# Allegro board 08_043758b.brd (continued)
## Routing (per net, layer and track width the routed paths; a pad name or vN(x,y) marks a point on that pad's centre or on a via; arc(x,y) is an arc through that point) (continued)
IO_L15_34_TX_D1: length 23.2
  TOP w0.102: U4.R13 48.72,29.34 48.43,29.34 48.23,29.14 45.92,29.14 v2(45.53,28.75) ; U5.D11 v2(32.35,28.08)
  L6_SIG w0.114: v2(32.35,28.08) 32.67,28.08 32.74,28 32.74,27.88 32.95,27.68 34.94,27.68 35.41,28.14 37.69,28.14 38.45,27.38 39.2,27.38 39.35,27.52 39.35,28.12 39.49,28.27 39.7,28.27 39.84,28.12 39.84,27.52 39.99,27.38 40.19,27.38 40.34,27.52 40.34,28.12 40.48,28.27 40.69,28.27 40.83,28.12 40.83,27.52 40.98,27.38 41.18,27.38 41.33,27.52 41.33,28.12 41.47,28.27 41.68,28.27 41.83,28.12 41.83,27.52 41.97,27.38 44.04,27.38 44.43,27.76 44.43,28.35 44.83,28.75 v2(45.53,28.75)
IO_L16_34_TX_D2: length 22.7
  TOP w0.102: v2(46.43,27.75) U4.R15 ; U5.E11 31.53,28.09 31.53,28.08 v2(31.54,28.07)
  L6_SIG w0.114: v2(31.54,28.07) 31.54,27.78 31.64,27.68 31.74,27.68 31.94,27.48 31.94,26.98 32.56,26.36 35.66,26.36 35.89,26.59 35.89,27.13 36.04,27.28 36.24,27.28 36.39,27.13 36.39,26.82 36.59,26.62 44.42,26.62 45.41,27.61 45.77,27.61 46.18,27.19 47.07,27.19 47.27,27.39 47.27,27.57 47.09,27.75 v2(46.43,27.75)
IO_L16_34_TX_D3: length 23.6
  TOP w0.102: U4.P11 49.12,30.54 48.53,30.54 47.73,29.75 43.82,29.75 v2(42.82,28.75) ; U5.D10 v2(32.34,28.88)
  L6_SIG w0.114: v2(32.34,28.88) 32.74,29.28 35.65,29.28 35.95,28.98 36.95,28.98 37.55,29.58 37.79,29.58 37.94,29.43 37.94,29.07 38.08,28.92 38.29,28.92 38.43,29.07 38.43,29.43 38.58,29.58 38.78,29.58 38.93,29.43 38.93,29.19 39.07,29.05 39.28,29.05 39.42,29.19 39.42,29.43 39.57,29.58 39.77,29.58 39.92,29.43 39.92,29.19 40.06,29.05 40.27,29.05 40.41,29.19 40.41,29.43 40.56,29.58 40.76,29.58 40.91,29.43 40.91,29.19 41.05,29.05 41.26,29.05 41.49,29.28 43.28,29.28 43.41,29.16 43.41,28.9 43.25,28.75 v2(42.82,28.75)
IO_L17_34_TX_D4: length 23.2
  TOP w0.102: U4.R11 48.33,30.95 v2(47.53,30.15) ; U5.E10 v2(31.54,28.88)
  L6_SIG w0.114: v2(31.54,28.88) 31.54,28.55 31.62,28.48 31.74,28.48 31.94,28.28 31.94,27.88 32.15,27.68 32.55,27.68 32.74,27.48 32.74,26.98 32.95,26.78 35.15,26.78 35.41,27.04 35.41,27.34 35.7,27.63 37.59,27.63 38.23,27 44.3,27 44.85,27.56 44.85,28.06 45.07,28.28 46.96,28.28 47.96,29.28 47.96,29.72 v2(47.53,30.15)
IO_L17_34_TX_D5: length 22.7
  TOP w0.102: U5.D9 v2(32.34,29.68) ; U4.R12 48.15,29.57 48.13,29.57 48,29.45 44.52,29.45 v2(43.83,28.75)
  L6_SIG w0.114: v2(32.34,29.68) 32.75,30.08 35.35,30.08 36.05,29.38 36.75,29.38 37.35,29.98 41.06,29.98 41.37,29.66 43.6,29.66 43.93,29.99 43.93,30.3 44.08,30.45 44.93,30.45 45.31,30.06 45.31,29.74 44.32,28.75 v2(43.83,28.75)
IO_L18_34_TX_D6: length 22.9
  TOP w0.102: U4.P14 49.13,28.14 49.13,27.55 48.95,27.37 44.4,27.37 v2(43.83,27.95) ; U5.E9 v2(31.54,29.68)
  L6_SIG w0.114: v2(43.83,27.95) 43.21,27.95 43.03,27.76 42.52,27.76 42.26,28.01 42.26,28.67 42.05,28.88 41.73,28.88 41.5,28.65 39.09,28.65 38.87,28.43 38.87,28 38.75,27.88 38.48,27.88 38.35,28 38.35,28.38 38.21,28.52 35.2,28.52 34.85,28.88 34.6,28.88 34.46,28.73 34.46,28.62 34.31,28.48 32.19,28.48 31.94,28.72 31.94,29.28 v2(31.54,29.68)
IO_L18_34_TX_D7: length 22.7
  TOP w0.102: U4.P13 49.12,28.94 48.42,28.94 48.23,28.75 46.63,28.75 46.63,28.75 v2(46.42,28.75) ; U5.D8 v2(32.34,30.48)
  L6_SIG w0.114: v2(46.42,28.75) 46.92,28.75 47.13,28.95 47.13,30.25 46.93,30.45 46.6,30.45 46.33,30.17 45.76,30.17 45.05,30.88 42.72,30.88 42.58,30.74 42.58,30.52 42.43,30.38 42.23,30.38 42.08,30.52 42.08,30.74 41.94,30.88 41.6,30.88 41.46,30.74 41.46,30.52 41.31,30.38 35.65,30.38 35.15,30.88 32.75,30.88 v2(32.34,30.48)
IO_L19_34_TX_D8: length 22.6
  TOP w0.102: v2(47.42,31.75) 47.82,32.15 49.93,32.15 U4.N9 ; U5.E8 v2(31.54,30.48)
  L6_SIG w0.114: v2(47.42,31.75) 44.93,31.75 44.86,31.68 38.85,31.68 38.71,31.82 37.69,31.82 37.45,31.58 37.45,31.32 37.31,31.18 37.1,31.18 36.96,31.32 36.96,31.63 36.81,31.78 36.6,31.78 36.46,31.63 36.46,31.32 36.31,31.18 36.11,31.18 35.96,31.32 35.96,31.76 35.75,31.98 32.45,31.98 31.94,31.47 31.94,30.88 v2(31.54,30.48)
IO_L19_34_TX_D9: length 23.4
  TOP w0.102: v2(49.93,32.95) 50.73,32.95 U4.M9 ; U5.D7 v2(32.34,31.28)
  L6_SIG w0.114: v2(49.93,32.95) 49.93,32.55 49.53,32.15 48.03,32.15 47.83,31.95 47.83,31.55 47.63,31.36 45.43,31.36 45.36,31.28 41.35,31.28 40.85,30.78 40.54,30.78 40.39,30.92 40.39,31.13 40.25,31.28 40.04,31.28 39.9,31.13 39.9,30.92 39.75,30.78 39.55,30.78 39.4,30.92 39.4,31.13 39.26,31.28 39.05,31.28 38.91,31.13 38.91,30.92 38.76,30.78 38.56,30.78 38.41,30.92 38.41,31.13 38.27,31.28 38.06,31.28 37.92,31.13 37.92,30.92 37.77,30.78 35.85,30.78 34.95,31.68 32.75,31.68 32.35,31.28 v2(32.34,31.28)
IO_L20_34_TX_D10: length 22.4
  TOP w0.102: v2(48.22,33.34) 48.23,33.35 U4.R8 ; U5.F8 v2(30.74,30.48)
  L6_SIG w0.114: v2(48.22,33.34) 48.13,33.05 47.83,32.75 47.83,32.35 47.62,32.15 45.37,32.15 45.06,32.46 45.06,33.02 44.85,33.22 36.04,33.22 35.56,33.71 34.17,33.71 33.94,33.48 33.94,33.03 33.39,32.48 32.14,32.48 31.68,32.02 31.48,32.02 31.14,31.68 31.14,30.88 30.75,30.48 v2(30.74,30.48)
IO_L20_34_TX_D11: length 22.8
  TOP w0.102: U4.R7 48.32,34.15 48.23,34.05 46.03,34.05 v2(44.53,32.55) ; U5.E7 v2(31.54,31.28)
  L6_SIG w0.114: v2(44.53,32.55) 44.53,32.21 44.4,32.08 40.49,32.08 40.33,32.24 40.33,32.66 40.19,32.81 39.98,32.81 39.84,32.66 39.84,32.26 39.69,32.11 39.49,32.11 39.34,32.26 39.34,32.54 39.2,32.68 38.99,32.68 38.85,32.54 38.85,32.38 38.7,32.24 38.5,32.24 38.35,32.38 38.35,32.54 38.21,32.68 38,32.68 37.86,32.54 37.86,32.38 37.71,32.24 37.51,32.24 37.36,32.38 37.36,32.54 37.22,32.68 37.01,32.68 36.87,32.54 36.87,32.38 36.72,32.24 36.14,32.24 35.52,32.85 34.4,32.85 33.79,32.24 32.31,32.24 31.85,31.78 31.65,31.78 31.54,31.68 v2(31.54,31.28)
IO_L21_34_CTRL_OUT4: length 32.1
  TOP w0.102: U4.M10 v2(50.73,31.35) ; U5.F6 v2(29.95,32.88)
  L5_SIG w0.114: v2(50.73,31.35) 51.13,30.95 51.13,30.34 50.93,30.14 48.93,30.14 48.26,29.47 46.91,29.47 45.93,30.45 45.53,30.45 44.02,31.95 44.02,32.85 43.26,33.61 43.26,34.38 41.27,36.38 36.57,36.38 35.28,37.67 32.1,37.67 31.6,37.16 31.6,36.73 31.14,36.28 31.14,33.47 30.95,33.28 30.35,33.28 v2(29.95,32.88)
IO_L21_34_CTRL_OUT5: length 30.6
  TOP w0.102: U5.F5 v2(29.95,33.67) ; U4.M11 v2(50.73,30.55)
  L5_SIG w0.114: v2(29.95,33.67) 30.34,34.07 30.34,34.68 29.95,35.08 29.95,36.65 31.72,38.43 40.55,38.43 45.23,33.75 45.23,32.31 45.69,31.85 46.33,31.85 47.03,31.15 47.03,30.88 47.36,30.54 47.93,30.54 48.34,30.95 50.33,30.95 v2(50.73,30.55)
IO_L22_34_CTRL_OUT6: length 32.3
  TOP w0.102: U5.F4 v2(29.94,34.48) ; v2(49.93,34.55) U4.N7
  L5_SIG w0.114: v2(29.94,34.48) 29.54,34.08 28.85,34.08 28.74,34.18 28.74,37.1 29.18,37.54 29.69,37.54 31.34,39.19 40.79,39.19 47.03,32.95 47.03,32.38 47.26,32.14 48.43,32.14 48.76,32.48 48.76,33.38 v2(49.93,34.55)
IO_L22_34_CTRL_OUT7: length 30.1
  TOP w0.102: U5.G4 v2(29.14,34.48) ; v2(49.93,33.75) U4.N8
  L5_SIG w0.114: v2(29.14,34.48) 29.55,34.88 29.55,36.76 31.6,38.81 40.67,38.81 46.23,33.25 46.23,32.35 47.23,31.34 48.73,31.34 49.53,32.15 49.53,33.35 v2(49.93,33.75)
IO_L23_35_SPI_CLK: length 70.5
  TOP w0.102: U5.J5 v2(27.55,33.68) ; U4.E11 v2(57.13,30.55)
  L5_SIG w0.114: v2(27.55,33.68) 27.15,33.28 24.56,33.28 21.91,30.62 21.91,23.61 28.17,17.35 34.52,17.35 35.28,16.58 42.14,16.58 42.77,17.22 54.18,17.22 54.47,17.51 57.92,17.51 58.83,18.42 58.83,25.95 59.33,26.45 59.33,28.05 59.13,28.25 59.13,30.74 58.93,30.95 57.53,30.95 v2(57.13,30.55)
IO_L23_35_SPI_ENB: length 66.4
  TOP w0.102: U4.E12 v2(57.13,29.75) ; U5.K6 v2(26.74,32.88)
  L5_SIG w0.114: v2(57.13,29.75) 57.53,30.15 58.13,30.15 58.33,29.95 58.33,28.44 59.03,27.74 59.03,26.65 58.53,26.15 58.53,18.76 57.67,17.89 54.09,17.89 53.8,17.6 42.52,17.6 41.88,16.96 37.56,16.96 36.93,17.6 28.42,17.6 22.21,23.81 22.21,30.5 24.18,32.48 26.34,32.48 v2(26.74,32.88)
IO_L24_35_SPI_DI: length 64.2
  TOP w0.102: U4.E13 v2(57.13,28.95) ; U5.J4 v2(27.54,34.48)
  L5_SIG w0.114: v2(27.54,34.48) U5.J4 27.94,32.38 27.24,31.68 24.23,31.68 23.55,30.99 23.55,30.78 23.77,30.56 23.77,30.35 23.63,30.21 23.42,30.21 23.2,30.43 22.99,30.43 22.8,30.24 22.8,24.24 28.67,18.36 53.29,18.36 53.58,18.65 57.26,18.65 57.93,19.32 57.93,27.94 57.23,28.64 v2(57.13,28.95)
IO_L24_35_SPI_DO: length 62.7
  TOP w0.102: U5.L6 v2(25.94,32.08) ; U4.F12 v2(56.33,29.75)
  L5_SIG w0.114: v2(25.94,32.08) 24.21,32.08 22.51,30.37 22.51,24.02 28.55,17.98 53.54,17.98 53.83,18.27 57.54,18.27 58.23,18.96 58.23,26.35 58.73,26.85 58.73,27.54 57.53,28.74 57.53,29.24 57.43,29.34 56.99,29.34 56.59,29.75 v2(56.33,29.75)
JTAG_TCK: length 49.9
  TOP w0.102: U4.G9 55.53,32.95 61.44,32.95 61.55,32.84 63.54,32.84 64.05,32.33 69.83,32.33 v1(70.34,31.82) ; TCK.1 60.3,8.71 62.84,8.71 P1.4
  L5_SIG w0.114: v1(70.34,31.82) 69.71,31.19 69.71,29.24 68.74,28.27 68.74,26.54 69.71,25.57 69.71,20.03 68.82,19.14 68.82,13.42 67.16,11.76 v1(67.16,11.12)
  BOTTOM w0.102: v1(67.16,11.12) 66.52,10.49 64.74,10.49 64.11,9.85 P1.4
JTAG_TDI: length 43.7
  TOP w0.102: TDI.1 69.82,6.8 69.82,7.44 69.06,8.2 67.41,8.2 P1.8 ; U4.L7 v2(51.53,34.55)
  L5_SIG w0.114: v2(51.53,34.55) 51.53,34.54 51.92,34.15 54.13,34.15 55.43,32.85 59.27,32.85 61.44,30.69 61.44,23.83 62.58,22.68 62.58,17.85 63.85,16.58 63.85,10.23 P1.8
JTAG_TDO: length 42.9
  TOP w0.102: TDO.1 69.82,8.07 69.19,8.71 66.65,8.71 P1.6 ; U4.L8 v2(51.53,33.75)
  L5_SIG w0.114: v2(51.53,33.75) 51.53,33.74 51.92,33.35 54.53,33.35 55.33,32.55 59.14,32.55 59.93,31.75 59.93,30.27 60.23,29.97 60.23,29.49 60.68,29.04 60.68,23.95 62.2,22.43 62.2,17.6 63.35,16.46 63.35,9.47 P1.6
JTAG_TMS: length 38.5
  TOP w0.102: P1.2 61.57,7.44 TMS.1 ; U4.L9 v2(51.53,32.95)
  L5_SIG w0.114: P1.2 62.84,16.33 61.82,17.35 61.82,22.17 60.3,23.7 60.3,28.84 59.92,29.22 59.92,29.93 59.53,30.31 59.53,31.35 59.13,31.75 52.73,31.75 v2(51.53,32.95)
PG_1P0V: length 21.6
  TOP w0.305: v1(92.94,21.92) 92.57,21.55 U3.16
  BOTTOM w0.203: v1(92.94,21.92) 93.7,22.68 93.7,30.48 89.76,34.41 89.76,37.67 89.13,38.3 R86.1
  BOTTOM w0.305: R6.2 v1(92.94,21.92)
PG_1P3V: length 94.8
  TOP w0.127: U12.4 v1(51.28,14.41) ; v2(58.73,32.15) 58.33,32.55 U4.C9 ; U7.5 v1(43.15,10.24) ; U1.5 22.28,10.91 22.45,10.74 v1(22.45,10.36)
  L5_SIG w0.127: v1(71.49,30.85) 71.49,30.46 70.47,29.45 70.47,28.91 71.24,28.14 71.24,26.41 70.47,25.64 v1(70.47,11.16)
  L6_SIG w0.127: v1(70.47,11.16) 69.58,10.27 63.74,10.27 58.91,15.1 55.87,15.1 55.18,14.41 v1(51.28,14.41) ; v1(71.49,30.85) 71.49,31.8 70.95,32.33 69.95,32.33 69.76,32.15 v2(58.73,32.15)
  BOTTOM w0.127: v1(22.45,10.36) 22.92,9.89 29.2,9.89 30,9.09 36.68,9.09 37.82,10.24 v1(43.15,10.24) 46.45,10.24 PG_1P3V.1 47.34,11.12 47.99,11.12 v1(51.28,14.41) ; v1(71.49,30.85) 71.49,31.44 R15.1 71.52,32.01 C47.1 72.95,32.01 R13.2
PG_1P8V: length 12
  TOP w0.203: v2(92.42,40.7) 92.3,41.05 U6.29 ; v2(91.79,47.49) 91.79,47.44 91.8,47.44 U6.13
  L5_SIG w0.305: v2(92.42,40.7) 92.42,41.08 94.21,42.87 94.21,46.3 93.57,46.94 92.3,46.94 91.79,47.44 v2(91.79,47.49)
  BOTTOM w0.305: R59.1 92.42,39.95 v2(92.42,40.7)
PG_1P35V: length 124.9
  TOP w0.127: v1(21.69,9.34) 21.05,9.98 U1.4 ; U7.4 42.22,9.64 42.52,9.34 v1(44.04,9.34)
  TOP w0.203: v2(92.43,48.21) 92.3,47.82 U6.12
  L5_SIG w0.127: v1(76.93,11.12) 76.19,11.87 76.19,16.75 77.71,18.27 77.71,19.54 79.36,21.19 79.36,27.29 79.87,27.8 79.87,32.88 85.58,38.59 85.58,45.32 88.47,48.21 v2(92.43,48.21)
  L6_SIG w0.127: v1(76.93,11.12) 76.55,11.5 71.98,11.5 70.24,9.76 63.49,9.76 59.04,14.21 57.14,14.21 56.63,13.7 50.66,13.7 47.99,11.03 44.97,11.03 44.04,10.11 v1(44.04,9.34)
  BOTTOM w0.127: v2(92.43,48.21) 92.43,47.44 91.92,46.94 85.44,46.94 83.54,45.03 R50.1 ; v1(21.69,9.34) 28.73,9.34 29.7,8.37 37.2,8.37 38.18,9.34 v1(44.04,9.34)
PL_GPIO0: length 50.1
  TOP w0.127: U4.K13 v2(52.33,28.95)
  L6_SIG w0.127: v2(52.33,28.95) 52.53,28.95 52.93,29.35 53.43,29.35 54.23,30.15 56.53,30.15 56.73,29.94 56.73,29.54 56.93,29.34 57.33,29.34 57.53,29.14 57.53,28.04 57.83,27.74 57.83,26.84 58.53,26.14 58.53,18.74 65.02,12.25 81.52,12.25 83.16,10.61 83.16,8.07 L10P.1
PL_GPIO1: length 55.5
  TOP w0.102: U4.M12 v2(50.73,29.75)
  L6_SIG w0.127: v2(50.73,29.75) 50.73,29.65 51.03,29.35 52.53,29.35 52.73,29.55 52.73,30.75 52.93,30.95 57.33,30.95 57.53,30.75 57.53,29.54 57.73,29.34 58.13,29.34 58.33,29.14 58.33,28.34 59.33,27.34 59.33,19.14 64.36,14.11 67.73,14.11 68.81,13.03 82.65,13.03 85.7,9.98 85.7,8.07 L12N.1
PL_GPIO2: length 52
  TOP w0.127: U4.R10 v2(48.25,31.75)
  L6_SIG w0.127: v2(48.25,31.75) 48.25,31.53 49.53,30.25 49.53,28.81 49.79,28.55 54.07,28.55 54.35,28.83 54.35,29.17 54.53,29.34 56.53,29.34 56.73,29.14 56.73,27.84 56.93,27.64 57.33,27.64 57.53,27.44 57.53,26.32 58.13,25.72 58.13,18.54 64.82,11.85 81.29,11.85 81.89,11.25 L24N.1
PS-SRST#: length 33.3
  TOP w0.127: v1(71.24,29.14) 70.04,29.14 69.84,28.94 64.23,28.94 63.74,29.44 R74.2 61.95,30.3 61.7,30.55 59.53,30.55 U4.B11 ; v2(75.54,44.38) U13.A4
  L5_SIG w0.127: v2(75.54,44.38) 75.54,32.24 73.44,30.14 72.24,30.14 v1(71.24,29.14)
PS_GPIO0: length 54.7
  TOP w0.102: U4.D8 v2(57.13,33.75)
  L5_SIG w0.127: v1(63.53,36.25) 62.73,35.45 60.03,35.45 59.23,34.65 58.63,34.65 58.13,34.15 57.53,34.15 v2(57.13,33.75)
  L6_SIG w0.127: v1(83.95,22.84) 84.35,22.44 84.35,18.57 92.05,10.87 MIO0.1
  BOTTOM w0.127: v1(83.95,22.84) 83.95,23.41 83.81,23.56 83.81,26.78 82.92,27.67 81.77,27.67 81.14,28.31 81.14,30.34 76.75,34.73 66.98,34.73 66.76,34.95 64.03,34.95 63.53,35.45 v1(63.53,36.25)
PS_GPIO1: length 55.8
  TOP w0.127: v1(72.34,29.14) 71.78,29.7 69.84,29.7 68.59,30.95 63.63,30.95 63.23,31.35 59.53,31.35 U4.B10
  L5_SIG w0.127: v1(72.34,29.14) 73.44,28.04 73.44,27.14 72.44,26.14 72.44,13.51 76.19,9.76 79.44,9.76 80.62,8.58 80.62,6.04 81.25,5.41 90.65,5.41 MIO10.1
PS_GPIO2: length 52.9
  TOP w0.127: U4.D6 v2(57.13,34.55)
  L5_SIG w0.127: v1(62.73,36.25) 62.23,35.75 59.73,35.75 58.93,34.95 57.53,34.95 v2(57.13,34.55)
  L6_SIG w0.127: v1(83.35,22.24) 83.35,18.93 89.51,12.77 MIO11.1
  BOTTOM w0.127: v1(62.73,36.25) 62.73,35.75 63.83,34.65 66.64,34.65 66.85,34.43 76.54,34.43 80.76,30.21 80.76,28.05 81.65,27.16 82.79,27.16 83.35,26.6 v1(83.35,22.24)
PS_GPIO3: length 51.1
  TOP w0.127: U4.B5 59.53,36.15 60.93,36.15 61.03,36.25 v1(61.73,36.25)
  L6_SIG w0.127: v1(82.15,22.24) 82.15,19.5 88.24,13.41 88.24,8.07 MIO09.1
  BOTTOM w0.127: v1(61.73,36.25) 63.63,34.35 66.54,34.35 66.74,34.15 76.31,34.15 80.38,30.08 80.38,27.8 82.15,26.03 v1(82.15,22.24)
PS_GPIO4: length 43.3
  TOP w0.127: U4.C13 v2(58.73,28.95)
  L6_SIG w0.127: v2(58.73,28.95) 58.73,28.45 60.93,26.24 60.93,18.14 63.43,15.63 66.75,15.63 68.97,13.41 85.19,13.41 86.97,11.63 MIO53.1
PS_GPIO5: length 45.8
  TOP w0.127: U4.D13 v2(57.93,28.95)
  L5_SIG w0.127: v1(83.16,11.5) 83.16,8.58 83.67,8.07 85.7,8.07 MIO49.1
  L6_SIG w0.127: v1(83.16,11.5) 82.01,12.65 68.68,12.65 67.62,13.71 64.16,13.71 58.93,18.94 58.93,27.24 57.93,28.24 v2(57.93,28.95)
PS_GPIO6: length 47
  TOP w0.127: v2(59.54,29.74) U4.B12
  L5_SIG w0.127: MIO48.1 86.08,11 v1(87.6,11)
  L6_SIG w0.127: v1(87.6,11) 87.6,12.39 86.21,13.79 69.19,13.79 66.95,16.03 63.63,16.03 61.33,18.34 61.33,26.34 59.13,28.54 59.13,29.34 v2(59.54,29.74)
PS_MIO01_500_QSPI0_SS_B: length 38.3
  TOP w0.127: U4.A5 64.13,35.75 64.54,36.15 65.14,36.15 65.89,36.9 65.89,39.5 68.35,41.97 v1(68.35,42.55) ; U13.C2 v2(72.61,48.31)
  L5_SIG w0.127: v2(72.61,48.31) 72.94,48.64 72.94,50.16 72.74,50.36 72.34,50.36 72.13,50.15 72.13,48.74 71.98,48.59 71.77,48.59 71.62,48.74 71.62,50.39 71.47,50.54 71.26,50.54 71.11,50.39 71.11,48.99 70.97,48.84 70.76,48.84 70.61,48.99 70.61,50.39 70.46,50.54 70.25,50.54 70.1,50.39 70.1,48.99 69.95,48.84 69.74,48.84 69.59,48.99 69.59,50.09 69.44,50.24 69.02,50.24 68.81,50.03 68.81,43 v1(68.35,42.55)
  BOTTOM w0.127: v2(72.61,48.31) 73.09,47.83 73.39,47.83 R14.2
PS_MIO02_500_QSPI0_IO0: length 33.8
  TOP w0.127: v1(74.14,33.6) 73.12,32.59 70.47,32.59 69.71,33.35 63.85,33.35 63.73,33.22 61.56,33.22 61.43,33.35 U4.A8 ; U13.D3 v2(70.61,47.31)
  L5_SIG w0.127: v1(74.14,33.6) 74.14,40.08 73.84,40.38 73.84,40.59 74.01,40.76 74.01,40.97 73.86,41.12 73.65,41.12 73.48,40.95 73.27,40.95 73.04,41.18 73.04,41.39 73.27,41.62 73.27,41.83 73.13,41.98 72.91,41.98 72.68,41.75 72.47,41.75 72.24,41.98 72.24,46.3 71.23,47.31 v2(70.61,47.31)
  BOTTOM w0.127: v2(70.61,47.31) 69.93,47.31 R120.1
PS_MIO03_500_QSPI0_IO1: length 37.5
  TOP w0.127: U4.A7 60.36,33.72 v2(61.65,33.72) ; U13.D2 v2(70.61,48.31)
  L5_SIG w0.127: v2(61.65,33.72) 61.65,34.32 61.95,34.62 63.09,34.62 64.05,35.57 64.26,35.57 64.87,34.96 65.08,34.96 65.23,35.1 65.23,35.32 64.61,35.93 64.61,36.14 64.76,36.29 64.97,36.29 65.89,35.37 66.1,35.37 66.25,35.52 66.25,35.73 65.33,36.65 65.33,36.86 65.48,37.01 65.69,37.01 66.31,36.39 66.52,36.39 66.67,36.54 66.67,36.75 66.05,37.37 66.05,37.58 66.2,37.73 66.41,37.73 67.66,36.48 67.87,36.48 68.02,36.63 68.02,36.84 66.77,38.09 66.77,38.55 67.27,39.05 68.94,39.05 69.19,39.3 69.19,41.11 69.04,41.26 68.32,41.26 68.17,41.41 68.17,41.62 68.32,41.77 69.04,41.77 69.19,41.92 69.19,46.78 69.34,46.93 69.8,46.93 69.95,47.08 69.95,47.29 69.8,47.44 69.34,47.44 69.19,47.59 69.19,47.95 69.54,48.31 v2(70.61,48.31)
  BOTTOM w0.127: R119.1 69.91,48.31 v2(70.61,48.31)
PS_MIO04_500_QSPI0_IO2: length 36
  TOP w0.127: U13.C4 v2(71.59,45.29) ; U4.C8 v2(57.93,33.75)
  L5_SIG w0.127: v2(57.93,33.75) 58.23,33.85 58.53,34.15 60.39,34.15 61.31,33.22 62.31,33.22 63.58,34.49 67.11,34.49 67.79,33.81 68,33.81 68.15,33.96 68.15,34.17 67.47,34.85 67.47,35.06 67.62,35.21 67.83,35.21 68.51,34.53 68.72,34.53 68.87,34.68 68.87,34.89 68.19,35.57 68.19,35.78 68.34,35.93 68.55,35.93 69.23,35.25 69.44,35.25 69.59,35.4 69.59,35.61 68.91,36.29 68.91,36.5 69.09,36.68 69.3,36.68 70.17,35.81 70.38,35.81 70.53,35.96 70.53,36.17 69.66,37.04 69.66,37.25 70.08,37.67 70.08,41.86 69.57,42.36 69.57,45.03 70.46,45.92 70.97,45.92 v2(71.59,45.29)
  BOTTOM w0.127: v2(71.59,45.29) 71.6,45.29 R121.1
PS_MIO05_500_QSPI0_IO3: length 73.5
  TOP w0.127: v1(70.34,30.93) 69.23,32.05 63.93,32.05 63.43,32.55 U4.A9 ; P1.5 65.38,4.26 66.65,2.99 JTAG_BOOT.1 ; U13.D4 v2(70.61,45.31)
  L5_SIG w0.127: P1.5 65.38,5.28 65.89,4.77 68.55,4.77 69.31,5.53 69.31,18.74 70.09,19.52 70.09,25.88 70.84,26.64 70.84,28.04 70.09,28.79 70.09,30.08 70.34,30.34 v1(70.34,30.93) 71.46,32.05 72.54,32.05 73.63,33.14 73.63,38.43 73.04,39.02 73.04,39.23 73.53,39.72 73.53,39.93 73.38,40.07 73.17,40.07 72.68,39.59 72.47,39.59 72.29,39.77 72.29,39.98 72.72,40.4 72.72,40.61 72.57,40.76 72.36,40.76 71.93,40.34 71.72,40.34 71.57,40.49 71.57,40.7 72,41.12 72,41.33 71.85,41.48 71.64,41.48 71.22,41.06 71.01,41.06 70.86,41.2 70.86,41.41 71.28,41.84 71.28,42.05 71.13,42.2 70.37,42.2 69.95,42.62 69.95,44.65 v2(70.61,45.31)
  BOTTOM w0.127: R122.1 70.61,44.54 v2(70.61,45.31)
PS_MIO06_500_QSPI0_SCLK: length 34.6
  TOP w0.127: U13.B2 v2(73.61,48.31) ; U4.A10 63.23,31.75 63.73,31.25 68.8,31.25 70,30.05 71.58,30.05 v1(72.38,30.85)
  L5_SIG w0.127: v2(73.61,48.31) 72.74,47.44 72.74,43.13 74.65,41.22 74.65,33.12 v1(72.38,30.85)
  BOTTOM w0.127: v2(73.61,48.31) 73.61,49.08 R116.1
PS_MIO07_500_USB_RESET_B: length 22.2
  TOP w0.127: U4.A12 60.1,29.97 v2(61.04,29.97) ; v1(76.05,30.81) 77.3,29.55 U15.27
  L6_SIG w0.127: v1(76.05,30.81) 74.12,30.81 73.24,29.93 73.24,29.24 72.64,28.64 70.84,28.64 69.44,30.04 68.34,30.04 68.14,30.24 61.3,30.24 v2(61.04,29.97)
  BOTTOM w0.127: v2(61.04,29.97) 61.04,29.64 R76.2
PS_MIO28_501_USB0_D4: length 23.7
  TOP w0.102: v1(66.65,24.58) 66.39,24.84 66.14,24.84 64.11,26.87 61.44,26.87 60.56,27.75 U4.A15 ; v1(73.25,24.48) U15.7
  L6_SIG w0.114: v1(66.65,24.58) 66.65,24.08 66.52,23.95 66.14,23.95 66.01,24.08 66.01,24.46 65.76,24.71 65.5,24.71 65.25,24.46 65.25,23.57 65.5,23.31 73.25,23.31 74.27,24.33 74.27,24.84 74.14,24.97 73.74,24.97 v1(73.25,24.48)
PS_MIO29_501_USB0_DIR: length 24.9
  TOP w0.102: U4.D11 v2(57.93,30.55) ; v1(74.27,30.17) 75.3,29.14 U15.31
  L6_SIG w0.114: v2(57.93,30.55) 58.33,30.14 58.93,30.14 59.32,30.53 59.85,30.53 60.24,30.14 60.24,29.34 60.67,28.9 63.41,28.9 63.56,28.76 63.56,28.29 63.7,28.14 63.91,28.14 64.05,28.29 64.05,28.56 64.2,28.7 64.4,28.7 64.55,28.56 64.55,28.29 64.69,28.14 64.9,28.14 65.04,28.29 65.04,28.56 65.19,28.7 65.39,28.7 65.54,28.56 65.54,28.29 66.69,27.14 70.34,27.14 71.55,28.34 72.84,28.34 73.74,29.24 73.74,29.65 v1(74.27,30.17)
PS_MIO30_501_USB0_STP: length 25.2
  TOP w0.102: U15.29 76.3,29.53 75.66,30.17 v1(75.28,30.17) ; v1(67.41,23.95) 66.52,23.95 63.98,26.49 61.31,26.49 60.55,27.25 59.62,27.25 U4.B15
  L6_SIG w0.114: v1(75.28,30.17) 75.28,27.63 74.01,26.36 73.25,26.36 72.74,25.85 72.74,24.84 71.6,23.7 68.04,23.7 67.79,23.95 v1(67.41,23.95)
PS_MIO31_501_USB0_NXT: length 24
  TOP w0.102: v1(72.87,27.51) 73.4,26.98 U15.2 ; U4.C12 v2(58.73,29.75)
  L6_SIG w0.114: v2(58.73,29.75) 58.93,29.75 59.43,30.24 59.73,30.24 59.93,30.05 59.93,28.75 61.04,27.63 61.77,27.63 61.91,27.49 61.91,26.89 62.06,26.74 62.26,26.74 62.41,26.89 62.41,27.49 62.55,27.63 62.76,27.63 62.9,27.49 62.9,26.89 63.05,26.74 63.25,26.74 63.4,26.89 63.4,27.49 63.54,27.63 63.75,27.63 63.89,27.49 63.89,26.89 64.04,26.74 64.24,26.74 64.39,26.89 64.39,27.49 64.53,27.63 64.74,27.63 64.88,27.49 64.88,26.89 65.03,26.74 70.45,26.74 71.72,28.01 72.36,28.01 v1(72.87,27.51)
PS_MIO32_501_USB0_D0: length 22.8
  TOP w0.102: v1(64.74,23.44) 63.22,24.97 60.55,24.97 60.3,25.22 58.39,25.22 56.73,26.88 U4.E15 ; U15.3 72.21,26.48 71.98,26.71 v1(71.98,27.47)
  L6_SIG w0.114: v1(64.74,23.44) 64.74,24.46 65.76,25.47 66.88,25.47 67.64,26.24 70.75,26.24 v1(71.98,27.47)
PS_MIO33_501_USB0_D1: length 22.1
  TOP w0.102: U15.4 72,25.98 v1(70.14,27.84) ; v2(58.73,30.54) 58.74,30.54 U4.C11
  L6_SIG w0.114: v2(58.73,30.54) 59.13,30.74 59.33,30.94 59.94,30.94 60.54,30.34 60.54,29.64 60.94,29.24 63.74,29.24 63.94,29.04 65.75,29.04 66.95,27.84 67.26,27.84 67.41,27.98 67.41,28.76 67.55,28.9 67.76,28.9 67.9,28.76 67.9,27.98 68.05,27.84 68.25,27.84 68.4,27.98 68.4,28.76 68.54,28.9 68.75,28.9 68.89,28.76 68.89,27.98 69.04,27.84 v1(70.14,27.84)
PS_MIO34_501_USB0_D2: length 25.3
  TOP w0.102: v1(65.38,22.43) 65.38,23.57 63.6,25.35 60.93,25.35 60.17,26.11 58.29,26.11 57.53,26.87 U4.D15 ; v1(73.25,25.48) U15.5
  L6_SIG w0.114: v1(65.38,22.43) 65.89,22.93 74.39,22.93 74.7,23.24 74.7,25.17 74.39,25.48 v1(73.25,25.48)
PS_MIO35_501_USB0_D3: length 23.7
  TOP w0.102: v1(71.22,25.47) 71.72,24.98 U15.6 ; v1(68.81,25.09) 68.3,25.6 66.39,25.6 64.36,27.63 61.69,27.63 60.78,28.55 U4.A14
  L6_SIG w0.114: v1(68.81,25.09) 68.3,25.09 68.04,25.35 68.04,25.73 68.17,25.85 69.31,25.85 69.44,25.73 69.44,24.84 69.57,24.71 69.94,24.71 70.08,24.86 70.08,25.71 70.23,25.85 70.43,25.85 70.58,25.71 70.58,24.86 70.72,24.71 71.47,24.71 71.98,25.22 71.98,25.83 71.83,25.98 71.35,25.98 71.22,25.85 v1(71.22,25.47)
PS_MIO36_501_USB0_CLK: length 23.1
  TOP w0.102: v1(67.41,25.09) 66.77,25.09 66.65,25.22 66.27,25.22 64.23,27.25 61.57,27.25 60.68,28.14 59.54,28.14 U4.B14 ; U15.1 v1(74.1,28.14)
  L6_SIG w0.114: v1(74.1,28.14) 74.1,28.52 74.23,28.65 74.78,28.65 74.9,28.52 74.9,27.76 73.89,26.74 72.62,26.74 72.36,26.49 72.36,25.09 71.35,24.08 70.5,24.08 70.24,24.33 70,24.33 69.75,24.08 69.5,24.08 69.25,24.33 69.01,24.33 68.76,24.08 68.43,24.08 v1(67.41,25.09)
PS_MIO37_501_USB0_D5: length 24.4
  TOP w0.102: v1(74.14,22.43) 74.52,22.43 74.8,22.71 U15.9 ; v1(66.39,22.43) 66.39,23.57 63.85,26.11 61.19,26.11 60.42,26.87 59.15,26.87 58.7,27.33 58.7,28.18 U4.C14
  L6_SIG w0.114: v1(74.14,22.43) 73.34,22.43 73.19,22.28 73.19,21.94 73.05,21.79 72.84,21.79 72.7,21.94 72.7,22.28 72.55,22.43 72.35,22.43 72.2,22.28 72.2,21.94 72.06,21.79 71.85,21.79 71.71,21.94 71.71,22.28 71.56,22.43 71.36,22.43 71.21,22.28 71.21,21.94 71.07,21.79 70.86,21.79 70.72,21.94 70.72,22.28 70.57,22.43 70.37,22.43 70.22,22.28 70.22,21.94 70.08,21.79 67.54,21.79 66.9,22.43 v1(66.39,22.43)
PS_MIO38_501_USB0_D6: length 25.5
  TOP w0.102: U4.A13 60.33,28.95 60.89,28.95 61.82,28.01 64.62,28.01 v1(66.52,26.11) ; v1(74.14,21.41) 75.3,22.57 U15.10
  L6_SIG w0.114: v1(66.52,26.11) 65.89,26.11 64.23,24.46 64.23,22.55 64.87,21.92 66.65,21.92 67.16,21.41 v1(74.14,21.41)
PS_MIO39_501_USB0_D7: length 25.5
  TOP w0.102: v1(66.39,21.41) 65.89,21.92 65.89,23.57 63.73,25.73 61.06,25.73 60.3,26.49 58.47,26.49 57.96,27 57.96,28.12 U4.D14 ; U15.13 76.8,22.53 v1(76.58,22.3)
  L6_SIG w0.114: v1(76.58,22.3) 75.18,20.9 66.9,20.9 v1(66.39,21.41)
PWR_CLK: length 39.1
  TOP w0.127: R5.2 v1(92.43,23.31) 91.66,22.55 U3.1
  L6_SIG w0.203: v1(79.77,42.43) 80.81,41.39 88.38,41.39 89.9,39.86 92.06,39.86 92.7,39.23 92.7,29.96 91.93,29.19 91.93,25.51 92.43,25.02 v1(92.43,23.31)
  BOTTOM w0.203: v1(79.77,42.43) R90.1 83.83,42.4 R89.2
RX1A_N: length 2.6
  TOP w0.229: C133.2 arc(23.54,36.54) 23.84,36.45 24.33,36.09 arc(24.64,35.93) 24.99,35.87 25.18,35.87 arc(25.38,35.82) U5.M2
RX1A_P: length 2.5
  TOP w0.229: C134.2 arc(23.72,37.31) 23.71,37.23 arc(23.76,37.06) 23.87,36.93 24.57,36.42 arc(24.77,36.32) 24.99,36.28 25.35,36.28 arc(25.49,36.34) U5.M1
SCL: length 21.9
  TOP w0.102: v2(49.53,26.05) 50.25,26.77 50.52,26.77 50.73,26.98 50.73,28.15 U4.M14
  TOP w0.127: v1(56.49,14.42) 56.49,15.14 R79.2 56.66,15.19 U11.2
  BOTTOM w0.127: v2(49.53,26.05) 49.53,26.04 50.14,25.44 50.14,23.82 50.52,23.44 50.52,18.11 54.46,14.17 55.6,14.17 55.85,14.42 v1(56.49,14.42)
SDA: length 24.3
  TOP w0.102: U4.N14 49.93,28.15 49.93,27.25 v2(49.53,26.85)
  TOP w0.127: v1(56.49,12.77) 56.49,13.48 R78.2 57.12,14.12 57.12,14.3 57.37,14.54 U11.3
  BOTTOM w0.127: v1(56.49,12.77) 57.12,13.41 57.12,14.55 56.74,14.93 55.85,14.93 55.47,14.55 54.58,14.55 50.9,18.23 50.9,23.57 50.52,23.95 50.52,25.86 v2(49.53,26.85)
SYNC: length 7.1
  TOP w0.305: U3.9 U3.10 ; U3.9 88.37,18.6 ; U3.9 88.81,17.85 ; U3.10 89.46,17.85 ; U3.10 U3.11 90.11,17.85
  TOP w1.524: 88.45,16.14 L4.1 89.44,14.04
TX1A_N: length 3.8
  TOP w0.229: U5.M8 25.42,31 arc(25.33,31.06) 25.23,31.08 25.11,31.08 arc(24.94,31.05) 24.79,30.95 24.16,30.32 arc(23.88,30.13) 23.56,30.07 23.22,30.07 arc(22.91,30.01) 22.65,29.83 L8.2
TX1A_P: length 3.8
  TOP w0.229: U5.M7 25.44,31.57 arc(25.35,31.51) 25.23,31.49 25.11,31.49 arc(24.78,31.42) 24.5,31.23 23.87,30.6 arc(23.73,30.51) 23.56,30.47 23.22,30.47 arc(22.91,30.54) 22.64,30.72 L9.2
TX_VCO_1P1V_SUPPLY: length 3.4
  TOP w0.305: U5.B11 v2(33.94,28.08) ; U5.A11 v2(34.74,28.08)
  BOTTOM w0.305: R52.1 C128.1 35.16,28.08 v2(34.74,28.08)
  BOTTOM w0.406: v2(33.94,28.08) v2(34.74,28.08)
UART_RX: length 48.8
  TOP w0.127: U4.C6 v2(57.93,35.35) ; P1.1 62.84,5.03 62.08,4.26 60.93,4.26 RX.1
  L5_SIG w0.127: v2(57.93,35.35) 57.53,35.75 56.93,35.75 56.73,35.55 56.73,33.55 56.93,33.35 59.28,33.35 60.93,31.7 64.87,31.7 66.52,30.05 66.52,27.38 65.5,26.36 65.5,24.23 67.79,21.95 67.79,13.41 66.14,11.76 65.51,11.76 v1(64.87,11.11)
  BOTTOM w0.127: P1.1 61.95,7.06 61.95,8.19 v1(64.87,11.11)
UART_TX: length 47
  TOP w0.127: U4.B7 v2(59.53,33.75) ; 64.11,4.9 P1.3
  TOP w0.152: TX.1 64.11,4.9
  L5_SIG w0.127: v2(59.53,33.75) 59.53,33.75 60.95,32.33 65.38,32.33 67.92,29.79 67.92,28.52 68.3,28.14 68.3,13.41 v1(66.01,11.12)
  BOTTOM w0.127: P1.3 64.11,5.41 63.85,5.15 62.08,5.15 61.57,5.66 61.57,8.71 64.62,11.76 65.38,11.76 v1(66.01,11.12)
UNNAMED_2_ADM7160V2_I254_VIN: length 4.1
  TOP w0.305: 50.46,16.12 U12.6 51.14,15.71
  TOP w0.762: 51.92,15.5 E2.2 52.8,16.33 ; 50.96,16.65 C173.1 51.6,17.35
UNNAMED_2_ADP1754_I93_SS: length 1.5
  TOP w0.203: U1.7 23.08,12.21 C2.1
UNNAMED_2_ADP1754_I233_SS: length 1.5
  TOP w0.203: U7.7 44.67,12.21 C12.1
UNNAMED_2_ADP2164_I29_EN: length 13.4
  TOP w0.203: C13.1 89.75,24.46 90.27,24.46 90.78,24.97 91.17,24.97 R10.1 R5.1 92.57,25.21 93.7,24.08 93.7,20.9
  TOP w0.305: 92.99,20.2 R1.1 ; R1.1 93.9,20.2 ; R1.1 93.44,20.61 ; C13.1 89.46,24.16 U3.3 ; 92.5,20.25 U3.14 U3.15 92.5,20.9
UNNAMED_2_ADP2164_I29_RT: length 3.4
  TOP w0.127: R10.2 91.02,23.82 90.4,23.82 v1(90.11,23.53) U3.2
  BOTTOM w0.127: v1(90.11,23.53) 90.88,23.53 R3.2
UNNAMED_2_FERRITE_I303_N1: length 11.7
  BOTTOM w0.508: VDD_GPO.1 40.61,63.95 40.61,61.67 39.03,60.08 E3.1
UNNAMED_2_RES_I251_N2: length 2.3
  BOTTOM w0.305: R4.2 85.09,19.53 84.68,19.12 R7.1
UNNAMED_3_ICXC7Z010_I16_PSCLK50: length 7
  TOP w0.127: U4.C7 58.73,34.55 60.24,34.55 60.42,34.36
  TOP w0.305: R12.2 61.95,34.74 61.57,34.36 60.42,34.36
UNNAMED_3_ICXC7Z010_I16_PSMIO75: length 5
  TOP w0.127: U4.D9 v2(57.93,32.15)
  BOTTOM w0.127: R83.2 61.75,32.46 59.15,32.46 59.03,32.59 58.37,32.59 v2(57.93,32.15)
UNNAMED_3_ICXC7Z010_I16_PSMIO85: length 8.8
  TOP w0.127: U4.B6 59.54,35.35 64.24,35.35 64.63,35.75 65.37,35.75 66.52,36.9 R84.1
UNNAMED_3_RES_I2_N1: length 2.6
  TOP w0.305: R9.1 71.6,36.15 R8.2 70.32,36.14 Y2.1
UNNAMED_3_RES_I48_N1: length 2.5
  TOP w0.305: R12.1 68.1,34.74 Y2.3
UNNAMED_4_ICMT41K256M16_I98_ZQ: length 4.2
  TOP w0.127: U2.L8 52.82,49.47 v2(52.82,46.57)
  BOTTOM w0.165: v2(52.82,46.57) 52.82,45.86 R165.1
UNNAMED_4_ICTPS51206_I44_S3: length 1.8
  TOP w0.127: U14.7 36.35,53.43 v2(36.24,53.54)
  BOTTOM w0.127: v2(36.24,53.54) 36.55,53.24 36.55,53.02 R222.2
UNNAMED_4_ICTPS51206_I44_S5: length 3.7
  TOP w0.127: v1(34.77,52.14) 35.26,52.63 U14.9
  BOTTOM w0.127: v1(34.77,52.14) 35.15,52.52 35.55,52.52 R221.2
UNNAMED_4_ICTPS51206_I44_VLDOIN: length 2.6
  TOP w0.203: 39.86,52.63 U14.2
  TOP w0.508: R44.2 40.74,52.44 ; R44.2 41.3,51.88 ; R44.2 40.18,51.88
UNNAMED_4_ICTPS51206_I44_VTTSNS: length 3
  TOP w0.203: U14.5 39.51,53.83 v2(39.85,54.18)
  BOTTOM w0.305: v2(39.85,54.18) 39.85,54.49 C80.1 41.2,54.87 R43.2
UNNAMED_4_ICXC7Z010_I26_PSDDR_1: length 3.4
  TOP w0.127: U4.H3 v2(54.73,37.75)
  BOTTOM w0.127: v2(54.73,37.75) 54.33,38.15 54.33,39.76 R40.1
UNNAMED_4_ICXC7Z010_I26_PSDDRVR: length 1.2
  TOP w0.127: U4.J3 v2(53.13,37.75)
  BOTTOM w0.127: R41.1 53.22,37.66 v2(53.13,37.75)
UNNAMED_5_CAP_I17_N1: length 24.1
  TOP w0.305: v2(56.33,34.55) 56.33,34.55 U4.F7
  L6_SIG w0.102: 57.53,33.19 57.53,33.95 57.33,34.15 56.73,34.15 56.73,33.21 56.75,33.19 56.19,33.19 55.93,33.45 U4.F7
  L6_SIG w0.305: 56.73,34.15 v2(56.33,34.55) U4.F7 ; 62.73,33.5 62.42,33.19 56.75,33.19
  L6_SIG w0.508: v1(67.34,40.06) 66.84,39.55 66.84,36.85 65.51,35.53 64.76,35.53 62.73,33.5
  BOTTOM w0.305: v2(56.33,34.55) 55.85,35.03 C98.1
  BOTTOM w0.508: C93.1 67.34,40.82 v1(67.34,40.06)
  BOTTOM w0.635: C93.1 67.36,41.97 E5.2
UNNAMED_5_CAP_I17_N2: length 29
  TOP w0.305: U4.J7 v2(53.93,34.55) 53.93,34.55 U4.H7 ; U4.F6 v2(56.33,35.35) ; U4.F8 v2(55.53,33.75) U4.G8
  L6_SIG w0.305: 54.73,34.55 54.73,34.05 55.03,33.75 v2(55.53,33.75) 55.53,33.05 55.86,32.71 63,32.71 63.34,33.05 ; 54.73,34.55 55.52,35.35 v2(56.33,35.35) ; 54.73,34.55 v2(53.93,34.55)
  L6_SIG w0.508: v1(68.34,40.06) 68.34,36.05 66.99,34.7 64.99,34.7 63.34,33.05
  BOTTOM w0.305: v2(56.33,35.35) 56.33,35.45 56.11,35.67 C98.2
  BOTTOM w0.508: v1(68.34,40.06) 68.34,40.83 C93.2
  BOTTOM w0.635: C93.2 E6.2
UNNAMED_5_DIOLED_I60_N: length 1.6
  TOP w0.127: DS1.C 107.58,21.41 R48.1
UNNAMED_5_DIOLED_I62_N: length 2.5
  TOP w0.127: DS2.C 107.67,14.04 106.97,14.74 R87.1
UNNAMED_5_ICXC7Z010_I13_DONE0: length 67.5
  TOP w0.127: U4.M7 v2(50.73,34.55) ; v1(101.95,19.38) 102.39,19.81 Q1.1
  L6_SIG w0.127: v2(50.73,34.55) 51.13,34.95 52.53,34.95 52.73,34.75 52.73,32.55 53.53,31.75 68.74,31.75 70.14,30.34 72.64,30.34 74.04,31.75 77.65,31.75 82.23,27.16 83.12,27.16 85.82,24.46 85.82,18.36 86.65,17.54 90.33,17.54 92.17,19.38 v1(101.95,19.38)
UNNAMED_5_ICXC7Z010_I13_INITB0: length 8.3
  TOP w0.127: v1(62.23,36.85) 64.42,36.85 R47.1 ; U4.D5 v2(57.93,36.15)
  L5_SIG w0.127: v1(62.23,36.85) 61.33,36.85 60.63,36.15 v2(57.93,36.15)
UNNAMED_5_ICXC7Z010_I13_PROGRAM: length 4
  TOP w0.127: U4.K6 v2(52.33,35.35)
  BOTTOM w0.127: R46.1 51.13,33.44 51.13,34.95 51.53,35.35 52.33,35.35 v2(52.33,35.35)
UNNAMED_5_ICXC7Z010_I13_VCCBATT: length 5.2
  TOP w0.127: U4.E6 v2(57.13,35.35)
  BOTTOM w0.127: R45.2 59.93,33.05 59.93,33.95 59.74,34.15 57.73,34.15 57.53,34.35 57.53,34.94 v2(57.13,35.35)
UNNAMED_5_ICXC7Z010_I13_VP0: length 20
  TOP w0.127: U4.G7 55.13,34.15 v2(55.53,34.55)
  L6_SIG w0.127: v2(55.53,34.55) 55.93,34.95 58.23,34.95 58.93,34.25 61.64,34.25 62.49,35.1 63.39,35.1 64.44,36.15 65.34,36.15 66.34,37.15 66.34,39.85 66.54,40.06 v1(66.54,40.86)
  BOTTOM w0.127: v1(66.54,40.86) 66.54,40.26 66.74,40.06 66.74,39.45 R11.2 R91.1
UNNAMED_5_RES_I61_N2: length 2.7
  TOP w0.127: R48.2 105.38,21.17 105.38,19.03 Q1.3
UNNAMED_5_RES_I63_N2: length 2.6
  TOP w0.127: R87.2 105.55,14.59 Q4.3
UNNAMED_7_AD9363_I13_RBIAS: length 3.7
  TOP w0.178: 25.14,33.68 25.94,33.68
  TOP w0.305: 25.94,33.68 U5.L4
  TOP w0.406: 25.14,33.68 24.78,33.68 arc(24.14,33.8) 23.6,34.16 R49.2
UNNAMED_7_AD9363_I13_XTALN: length 4.5
  TOP w0.203: C123.2 24.93,23.57 C124.1 24.93,27.06 U5.M12
UNNAMED_7_CAP_I22_N2: length 1
  BOTTOM w0.305: C126.2 R51.1
UNNAMED_7_CAP_I30_N1: length 1
  BOTTOM w0.305: R52.2 36.15,26.38 C127.1
UNNAMED_7_CAP_I39_N2: length 2.2
  TOP w0.483: T5.4 arc(19.12,31.31) C132.2
UNNAMED_7_CAP_I40_N2: length 2.2
  TOP w0.483: T5.6 arc(19.12,29.22) C131.2
UNNAMED_7_CAP_I51_N1: length 2.2
  TOP w0.483: T1.4 22.98,38.26 arc(23.15,38.01) C134.1
UNNAMED_7_CAP_I52_N1: length 2.2
  TOP w0.483: C133.1 22.68,36.76 22.18,36.76 arc(21.38,36.86) T1.6
UNNAMED_7_CAP_I53_N1: length 2.8
  TOP w0.203: Y3.3 24.99,20.14 C123.1
UNNAMED_7_CNBNC5P_I57_CNTR: length 17.8
  TOP w0.483: T1.3 12.3,44.89 10.55,45.9 arc(9.67,46.27) 8.73,46.39 RX1A.1
UNNAMED_7_CNBNC5P_I58_CNTR: length 18
  TOP w0.483: TX1A.1 7.44,22.95 arc(8.33,23.12) 9.08,23.62 9.67,24.21 arc(10.21,25.03) 10.41,26 10.41,28.47 arc(11.3,30.64) 13.48,31.54 T5.3
UNNAMED_9_ADM1177_I23_GATE: length 1.9
  TOP w0.203: Q3.1 86.41,60.96 v1(85.6,60.14)
  BOTTOM w0.203: U10.10 v1(85.6,60.14)
UNNAMED_9_ADM1177_I23_ON: length 3
  BOTTOM w0.203: U10.3 91.69,58.55 R71.2
  BOTTOM w0.254: R72.1 R71.2
UNNAMED_9_ADM1177_I23_SENSE: length 5.6
  TOP w0.762: Q3.3 89.8,60.02 ; Q3.3 88.85,59.26 ; Q3.3 88.85,60.78
  TOP w1.016: 90.32,62.56 R73.2 91.22,61.6
  BOTTOM w0.203: U10.2 88.9,59.05 v1(88.76,58.91)
UNNAMED_9_ADM1177_I23_SS: length 1.9
  BOTTOM w0.305: U10.9 84.47,59.05 C155.1
UNNAMED_9_ADM1177_I23_TIMER: length 1.6
  BOTTOM w0.203: C156.1 89.94,56.04 U10.5
UNNAMED_9_ADM1177_I23_VCC: length 8.6
  TOP w1.016: 93.13,61.6 R73.1 94.03,62.56
  TOP w1.27: 93.57,60.53 D3.C 94.77,59.13
  BOTTOM w0.203: U10.1 91.7,59.55 R71.1 91.83,60.44 92.43,61.03 v1(93.06,61.03)
UNNAMED_9_ADP198_I329_VOUT: length 8.2
  TOP w0.254: 103.47,43 U16.A2 103.86,43.38
  TOP w0.635: C171.1 103.8,42.68 ; C171.1 103.8,41.28 ; C171.1 104.43,41.98 ; C172.1 104.43,40.21 ; C172.1 103.8,40.9 ; C172.1 103.8,39.51
  BOTTOM w0.508: 103.21,37.69 F1.1 ; F1.1 103.74,38.3 ; F1.1 103.21,38.91 ; 103.71,39.65 R88.1 ; R88.1 103.71,40.76 ; R88.1 104.24,40.21
  vias: v1(103.6,41.09) v1(103.6,39.32) v1(104.37,41.09) v1(104.37,39.32)
UNNAMED_9_ADP2114_I196_EN1: length 4.1
  TOP w0.127: U6.28 v2(91.8,40.71)
  BOTTOM w0.203: v2(91.8,40.71) 91.02,39.94 R85.2 R86.2
UNNAMED_9_ADP2114_I196_FREQ: length 1.6
  TOP w0.305: U6.3 96.09,43.52 R53.2
UNNAMED_9_ADP2114_I196_OPCFG: length 1.8
  TOP w0.305: U6.6 95.23,45.02 v1(95.35,44.9)
  BOTTOM w0.508: R54.1 94.47,44.9 v1(95.35,44.9)
UNNAMED_9_ADP2114_I196_SS1: length 2.1
  TOP w0.203: U6.30 92.8,41.09 v2(93.06,40.71)
  BOTTOM w0.254: C7.2 93.38,40.4 v2(93.06,40.71)
UNNAMED_9_ADP2114_I196_SS2: length 1.9
  TOP w0.203: v2(93.06,47.83) 92.8,47.44 U6.11
  BOTTOM w0.305: C139.2 93.06,47.3 v2(93.06,47.83)
UNNAMED_9_ADP2114_I196_SW1: length 3.1
  TOP w0.305: 88.9,42.52 U6.24 89.51,42.43 89.51,42.24 89.25,41.98 ; 88.9,43.02 U6.23
  BOTTOM w0.203: R89.1 v1(87.24,42.4)
UNNAMED_9_ADP2114_I196_SW3: length 2.1
  TOP w0.305: 88.9,45.52 U6.18 ; 88.9,46.02 U6.17 89.48,46.13 89.48,46.34 89.28,46.54
UNNAMED_9_CAP_I163_N1: length 7.2
  TOP w0.762: 82.71,41.22 L3.2 83.7,39.13 ; 83.72,37.67 C146.1 84.62,38.72
  TOP w1.016: 83.12,37.37 L5.1 81.76,38.15
UNNAMED_9_CAP_I214_N2: length 1
  BOTTOM w0.508: R60.2 C147.2
UNNAMED_9_CAP_I224_N2: length 1
  TOP w0.305: R61.2 C144.2
UNNAMED_9_CHOKE4P_I327_N2: length 6.9
  TOP w0.102: L6.2 99.94,33.71 99.67,33.98 99.67,34.37 100.16,34.86 102.39,34.86 ; 102.53,34.86 D1.C 102.39,34.86 ; 102.53,34.86 104,34.86 104.19,34.67 P2.3 ; 102.53,34.86 102.39,34.86
UNNAMED_9_CHOKE4P_I327_N3: length 7.2
  TOP w0.102: L6.3 99.14,33.71 99.4,33.97 99.4,34.48 100.05,35.13 101.31,35.13 ; 101.31,35.13 103.99,35.13 104.18,35.32 P2.2 ; 101.31,35.13 101.32,35.14 D2.C
UNNAMED_9_CN5P3SHLD_I255_N6: length 3.8
  TOP w0.635: 107.69,39.61 P2.SH3 106.48,38.84
  TOP w0.762: 106.46,40 R55.1 107.42,40.9
UNNAMED_9_CN5P3SHLD_I256_N6: length 4.1
  TOP w0.635: P3.SH1 106.21,48.27
  TOP w0.762: 104.3,48.02 R58.1 105.21,47.06 ; 107.69,47.51 P3.SH1
UNNAMED_9_ICNCP339_I277_EN: length 2.9
  TOP w0.203: R69.1 101.45,50.73 R68.2 101.97,51.9 102.4,52.34 U8.C2
UNNAMED_9_ICNCP339_I278_EN: length 6.7
  TOP w0.203: U9.C2 98.65,38.56 98.28,38.92 R70.2 98.14,39.57 99.16,40.59 99.16,41.73 v1(99.92,42.49)
  BOTTOM w0.203: v1(99.92,42.49) 99.92,43.36 Q2.3
UNNAMED_9_RES_I270_N1: length 3.8
  BOTTOM w0.305: R67.1 R66.2 103.49,45.43 102.51,44.45 Q2.1
UNNAMED_11_ICUSB3320C_I29_RBIAS: length 1.6
  TOP w0.127: v1(79,28.32) U15.24
  BOTTOM w0.127: v1(79,28.32) 79,27.81 R77.1
UNNAMED_11_ICUSB3320C_I29_REFCL: length 2.2
  TOP w0.254: R82.1 77.8,29.4 U15.26
UNNAMED_11_RES_I67_N2: length 1.5
  TOP w0.305: Y1.3 78.46,32.47 R82.2
USB_ID: length 30.8
  TOP w0.127: v1(81.77,29.07) 81.77,28.56 80.19,26.98 U15.23 ; P2.4 v1(103.87,34.02)
  L5_SIG w0.127: v1(103.87,34.02) 103.11,34.78 93.2,34.78 92.44,34.02 92.44,32.5 89.65,29.7 82.41,29.7 v1(81.77,29.07)
USB_OTG_CPEN: length 42.5
  TOP w0.127: v1(80.76,22.97) 79.36,22.97 79,23.33 U15.17 ; v1(100.19,44.56) 100.87,43.88 U16.B1
  L5_SIG w0.127: v1(100.19,44.56) 97.74,44.56 96.81,43.63 96.81,37.28 94.69,35.16 93.05,35.16 92.06,34.18 92.06,32.65 89.49,30.08 81.52,30.08 81.01,29.58 81.01,28.56 81.27,28.31 81.27,24.75 80.76,24.24 v1(80.76,22.97)
USB_OTG_N: length 24.6
  TOP w0.102: U15.19 79.31,24.98 79.42,24.86 83.06,24.86 85.58,27.39 97.02,27.39 99.41,29.78 99.41,31.19 99.14,31.46 L6.4
USB_OTG_P: length 25
  TOP w0.102: L6.1 99.94,31.46 99.67,31.19 99.67,29.67 97.13,27.12 85.69,27.12 83.17,24.6 79.41,24.6 79.29,24.48 U15.18
USB_VBUS_OTG: length 32.5
  TOP w0.254: v1(82.92,29.07) 80.5,26.65 79.74,26.65 79.57,26.48 U15.22
  L5_SIG w0.508: v1(82.92,29.07) 89.9,29.07 93.46,32.62 v1(93.46,33.64) v1(94.22,33.64)
  BOTTOM w0.508: v1(93.46,33.64) v1(94.22,33.64) 94.22,36.6 96.87,39.25 100.85,39.25 101.8,40.21 R88.2
USR_BTN: length 67.2
  TOP w0.127: U4.B9 59.53,32.15 63.33,32.15 63.83,31.65 68.94,31.65 70.25,30.34 70.6,30.34 70.98,30.72 70.98,31.27 71.23,31.53 73.31,31.53 75.04,33.26 75.04,35.42 77.71,38.08 v1(79.49,38.08)
  TOP w0.203: v1(105.81,22.68) S1.1
  L6_SIG w0.127: v1(79.49,38.08) 82.48,38.08 85.82,34.74 85.82,28.27 89.38,24.71 89.38,23.19 89.76,22.81 90.65,22.81 92.17,21.28 100.18,21.28 100.68,21.79 104.92,21.79 v1(105.81,22.68)
  BOTTOM w0.203: v1(79.49,38.08) 79.87,37.7 R57.2
USR_LED: length 57.8
  TOP w0.102: U4.D10 v2(57.93,31.35)
  TOP w0.127: v1(100.68,12.98) R75.1 103.15,12.98 Q4.1
  L6_SIG w0.127: v2(57.93,31.35) 58.33,30.94 58.93,30.94 59.34,31.35 67.84,31.35 67.84,31.35 68.74,30.44 69.54,30.44 70.04,29.94 72.75,29.94 74.15,31.35 76.44,31.35 78.34,29.45 78.73,29.45 85.44,22.73 85.44,18.11 90.57,12.98 v1(100.68,12.98)
VTT_0P75: length 29.8
  TOP w0.203: 39.98,53.03 U14.3
  TOP w0.889: 41.97,54.47 C79.1 41.12,53.67
  BOTTOM w0.305: 50.42,46.84 R28.2 ; R28.2 49.96,47.25 ; R28.2 R30.2 ; R33.2 54.78,57.09 ; R33.2 54.32,57.5 ; R33.2 R39.2 ; 46.5,53.61 R34.2 ; R34.2 R17.2 ; R34.2 46.09,54.07 ; R22.2 46.6,52.33 ; R22.2 R29.2 ; R22.2 46.19,51.87 ; 46.09,54.88 R17.2 ; R17.2 R26.2 46.09,55.68 ; 51.22,46.84 R30.2 ; R30.2 R21.2 ; 52.02,46.84 R21.2 ; R21.2 R38.2 ; R16.2 51.92,57.5 ; R16.2 R35.2 ; R16.2 R23.2 ; 46.19,51.07 R29.2 ; R29.2 46.6,50.27 R18.2 ; 51.49,51.67 R36.2 ; R35.2 52.72,57.5 ; R35.2 R39.2 ; 46.19,49.47 R27.2 ; R27.2 R18.2 ; R27.2 46.6,49.01 ; 46.6,47.81 R20.2 ; R20.2 46.6,48.73 ; R20.2 46.19,48.27 ; R19.2 49.37,47.25 ; R19.2 48.92,46.84 ; R19.2 48.46,47.25 ; R23.2 51.12,57.5 ; R23.2 R24.2 50.32,57.5 ; 42.25,54.38 R43.1 42.81,54.94 ; R18.2 46.19,50.27 ; R25.2 48.12,57.5 ; C101.1 44.97,57.6 ; C101.1 44.41,57.05 ; C101.1 44.41,58.16 ; R31.2 R37.2 51.49,53.27 ; 51.49,52.47 R32.2 ; R39.2 53.52,57.5
  vias: v1(42.52,54.05) v1(42.52,53.29) v1(43.28,54.05) v1(43.28,53.29)
VTTVREF: length 79.7
  TOP w0.152: 52.02,51.17 v2(52.02,50.27)
  TOP w0.203: C84.1 35.52,53.97 36.51,53.97 36.65,53.83 U14.6
  TOP w0.305: U2.M8 v2(52.02,50.27) ; U4.F4 v2(56.33,36.95) ; U2.H1 v2(55.22,55.87)
  TOP w0.508: C84.1 35.41,55 C81.1 36.23,57.8 37.05,58.62 45.82,58.62 ; 45.82,58.62 48.36,58.62 49.25,57.73 53.69,57.73 54.58,58.62 v1(55.22,58.62) v2(55.22,55.87) ; 45.82,58.62 45.82,53.77 46.92,52.67 51.12,52.67 52.02,51.77 52.02,51.17
  BOTTOM w0.152: 56.32,38.56 55.92,38.16 55.92,37.36 56.33,36.96 v2(56.33,36.95) 56.72,37.34 56.72,38.16 56.32,38.56
  BOTTOM w0.305: v2(55.22,55.87) 55.71,55.87 C63.2 ; v2(52.02,50.27) 52.5,49.78 C102.1 ; 57.92,40.26 C99.2
  BOTTOM w0.508: v1(55.22,58.62) 56.49,58.62 57.53,57.58 62.53,57.58 63.33,56.78 63.33,45.78 57.92,40.37 57.92,40.26 57.12,40.26 56.52,39.66 56.52,38.76 56.32,38.56

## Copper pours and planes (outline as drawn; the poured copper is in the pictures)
1V8 on TOP (solid shape): 38.61,10.59 38.8,10.59 38.9,10.54 39.01,10.53 39.69,10.53 39.74,10.53 39.79,10.54 39.85,10.54 39.85,10.49 39.91,10.49 39.91,10.43 39.89,10.38 39.89,10.33 39.89,9.64 39.9,9.56 39.93,9.48 39.93,9.22 41.76,9.22 41.76,8.96 41.74,8.96 41.74,8.93 41.68,8.86 41.21,8.86 41.21,8.05 41.68,8.05 41.74,7.98 41.74,7.95 41.76,7.95 41.76,6.68 39.34,6.68 37.56,8.46 37.56,11.38 38.61,11.38
1V8 on TOP (solid shape): 17.02,10.64 17.15,10.64 17.27,10.56 17.42,10.53 18.1,10.53 18.15,10.53 18.2,10.54 18.26,10.54 18.26,10.49 18.32,10.49 18.32,10.43 18.3,10.38 18.3,10.33 18.3,9.64 18.31,9.56 18.34,9.48 18.34,9.22 19.86,9.22 19.86,9.27 19.98,9.26 20.05,9.27 20.13,9.24 20.17,9.17 20.17,8.96 20.15,8.96 20.15,8.93 20.09,8.86 19.62,8.86 19.62,8.05 20.09,8.05 20.15,7.98 20.15,7.95 20.17,7.95 20.17,6.68 18.51,6.68 15.97,9.22 15.97,11.38 17.02,11.38
1V8 on TOP: 39.34,51.13 39.34,44.14 41.76,44.14 41.76,51.13
1V8 on TOP: 84.94,36.52 81.13,36.52 81.13,30.68 85.44,30.68 85.44,36.01
1V8 on TOP: 34.64,13.03 31.34,13.03 31.34,11.5 31.85,11 31.85,9.09 34.64,9.09
1V8 on BOTTOM: 82.66,30.68 85.19,30.68 85.19,35.38 82.66,35.38
1V8 on BOTTOM: 66.27,26.87 63.6,26.87 63.6,33.09 66.27,33.09
1V8 on L8_PWR: 59.66,5.22 59.66,11.25 47.78,11.25 42.7,6.17 17.75,6.17 17.75,13.15 20.74,13.15 21.69,14.11 36.8,14.11 36.8,21.41 39.34,21.41 39.34,49.98 84.43,49.98 84.43,16.01 97.76,16.01 97.76,5.22
1V35 on TOP: 67.54,52.78 63.73,52.78 63.73,55.32 67.54,55.32
1V35 on TOP: 81.25,45.29 81.25,52.14 80.36,53.03 80.36,55.83 84.43,55.83 84.43,45.29 ; 1 cut-out
1V35 on TOP: 55.73,41.96 55.73,44.17 58.32,44.17 58.32,41.96
1V35 on L3_PWR: 46.14,33.79 38.71,41.23 38.71,59.51 50.93,59.51 52.28,59.26 53.63,59.51 77.13,59.51 77.13,56.33 83.48,56.33 83.48,41.09 78.4,41.09 78.4,35.38 57.57,35.38 55.67,37.28 51.09,37.28 51.09,33.79
GND on TOP: outline of 86 points within 0.64,0.64 108.5,68.7 ; 52 cut-outs
GND on TOP: 79.6,43.63 79.6,44.78 89.13,44.78 89.51,45.16 90.4,45.16 90.4,45.92 93.7,45.92 93.7,42.75 90.4,42.75 90.4,43.38 89.25,43.38 89.19,43.45 90.25,43.45 90.25,43.85 88.93,43.85 88.93,43.63 ; 2 cut-outs
GND on BOTTOM: 104.08,4.29 80.14,1.63 56.08,0.64 56.08,6.28 52.28,10.08 48.48,6.28 48.48,3.88 32.99,3.88 32.99,1.27 20.15,2.3 7.34,3.8 3.99,4.28 0.64,4.78 0.64,64.55 1.7,64.72 1.7,64.72 16.68,66.68 31.72,67.98 31.72,67.98 48.48,67.98 48.48,63.06 48.6,62.12 48.94,61.24 48.94,59.89 49.78,59.89 49.78,60.2 51.4,59.36 53.21,59.38 53.21,58.95 55.01,58.95 55.01,59.15 55.65,59.15 55.65,61.31 55.97,62.16 56.08,63.06 56.08,68.7 77.28,67.91 98.4,65.83 98.4,41.09 94.91,37.6 94.91,35.7 95.54,36.33 102.21,36.33 102.53,36.01 102.53,29.35 108.48,29.35 108.48,26.92 108.5,26.92 108.5,15.52 108.5,10.08 108.5,8.6 107.49,5.87 104.95,4.43 ; 73 cut-outs
GND on L2_GND: 104.08,4.29 80.14,1.63 56.08,0.64 56.08,6.28 52.28,10.08 48.48,6.28 48.48,0.68 24.49,1.9 0.64,4.78 0.64,64.55 24.49,67.44 48.48,68.66 48.48,63.06 52.28,59.26 56.08,63.06 56.08,68.7 77.28,67.91 98.4,65.83 98.4,41.23 97.13,39.96 97.13,36.33 104.93,36.33 105.07,36.2 105.07,34.11 102.53,34.11 102.53,29.35 108.5,29.35 108.5,10.08 108.5,8.61 107.49,5.87 104.95,4.43
GND on L3_PWR: 104.08,4.29 80.14,1.63 56.08,0.64 56.08,6.28 52.28,10.08 48.48,6.28 48.48,0.68 24.49,1.9 0.64,4.78 0.64,64.55 24.49,67.44 48.48,68.66 48.48,63.06 48.84,61.45 49.84,60.14 38.07,60.14 38.07,51.25 23.47,51.25 23.47,43.5 25.88,41.09 30.96,41.09 35.53,36.52 35.53,23.31 32.04,23.31 32.04,10.17 32.23,9.98 46.33,9.98 46.33,17.28 50.46,17.28 50.46,10.61 54.77,10.61 57.31,8.07 108.47,8.07 107.32,5.67 104.95,4.43
GND on L4_GND, L7_GND, L9_GND: 104.08,4.29 80.14,1.63 56.08,0.64 56.08,6.28 52.28,10.08 48.48,6.28 48.48,0.68 24.49,1.9 0.64,4.78 0.64,64.55 24.49,67.44 48.48,68.66 48.48,63.06 52.28,59.26 56.08,63.06 56.08,68.7 77.28,67.91 98.4,65.83 98.4,41.23 97.13,39.96 97.13,36.33 102.53,36.33 102.53,29.35 108.5,29.35 108.5,10.08 108.5,8.61 107.49,5.87 104.95,4.43
GND on L5_SIG: 104.08,4.29 80.14,1.63 56.08,0.64 56.08,6.28 52.28,10.08 48.48,6.28 48.48,0.68 24.49,1.9 0.64,4.78 0.64,64.55 24.49,67.44 48.48,68.66 48.48,63.06 52.28,59.26 56.08,63.06 56.08,68.7 77.28,67.91 98.4,65.83 98.4,44.26 97.36,44.26 97.36,40.06 97.13,39.82 97.13,37.6 95.54,36.01 95.54,35.06 102.53,35.06 102.53,29.35 108.5,29.35 108.5,15.52 108.5,8.6 107.49,5.87 104.95,4.43 ; 45 cut-outs
GND on L6_SIG: 104.08,4.29 80.14,1.63 56.08,0.64 56.08,6.28 52.28,10.08 48.48,6.28 48.48,0.68 24.49,1.9 0.64,4.78 0.64,64.55 24.49,67.44 48.48,68.66 48.48,63.06 52.28,59.26 56.08,63.06 56.08,68.7 77.28,67.91 98.4,65.83 98.4,41.09 97.13,39.82 97.13,36.33 102.21,36.33 102.53,36.01 102.53,29.35 108.5,29.35 108.5,15.52 108.5,8.6 107.49,5.87 104.95,4.43 ; 27 cut-outs
GND on L8_PWR: 20.29,22.04 20.29,40.46 35.53,40.46 35.53,48.71 38.71,48.71 38.71,22.04 36.3,22.04 29.95,28.39 27.28,28.39 27.28,22.04
GND on L8_PWR: 104.08,4.29 80.14,1.63 56.08,0.64 56.08,6.28 52.28,10.08 48.48,6.28 48.48,0.68 24.49,1.9 0.64,4.78 0.64,64.55 24.49,67.44 48.48,68.66 48.48,63.06 48.67,61.86 49.24,60.78 34.26,60.78 34.26,59.83 10.77,59.83 10.77,13.15 17.12,13.15 17.12,5.53 42.97,5.53 48.05,10.61 59.03,10.61 59.03,4.58 98.4,4.58 98.4,16.65 85.06,16.65 85.06,60.78 55.32,60.78 55.88,61.86 56.08,63.06 56.08,68.7 77.28,67.91 98.4,65.83 98.4,41.23 97.13,39.96 97.13,36.33 102.53,36.33 102.53,29.35 108.5,29.35 108.5,8.61 107.49,5.87 104.95,4.43
PGND on TOP: 105.76,42.11 107.16,42.11 107.16,45.03 105.76,45.03
PGND on TOP: 103.1,42.87 103.1,43.51 101.45,43.51 101.45,38.94 102.84,38.94 102.84,42.62
PGND on TOP: 102.72,49.48 102.72,45.29 101.06,45.29 101.06,49.48
PGND on TOP: 99.03,55.57 103.73,55.57 103.73,57.48 99.03,57.48
PGND on L2_GND, L3_PWR, L4_GND, L7_GND, L9_GND: 103.16,29.98 103.16,33.47 105.7,33.47 105.7,36.46 105.2,36.97 97.76,36.97 97.76,39.69 99.03,40.96 99.03,65.75 101.56,65.4 104.08,65.04 104.95,64.9 107.49,63.47 108.5,60.73 108.5,57.47 108.5,55.88 107.56,55.88 106.81,55.57 106.5,54.82 106.81,54.07 107.56,53.76 108.5,53.76 108.5,51.13 107.56,51.13 106.81,50.82 106.5,50.07 106.81,49.32 107.56,49.01 108.5,49.01 108.5,38.1 107.56,38.1 106.81,37.79 106.5,37.04 106.81,36.29 107.56,35.98 108.5,35.98 108.5,33.35 107.56,33.35 106.81,33.04 106.5,32.29 106.81,31.54 107.56,31.23 108.5,31.23 108.5,29.98
PGND on L5_SIG, L6_SIG: 97.76,36.97 97.76,39.51 99.03,40.78 99.03,61.29 106.5,61.29 106.5,47.28 107.29,46.49 107.29,40.14 106.5,39.35 106.5,36.55 106.84,36.21 106.84,33.16 106.5,32.81 106.5,29.98 103.16,29.98 103.16,33.16 103.48,33.47 105.7,33.47 105.7,36.33 105.07,36.97
VCCPINT on TOP: 56.03,21.74 64.18,21.74 64.18,24.09 56.03,24.09
VCCPINT on TOP: 76.81,13.03 86.84,13.03 86.84,18.23 76.81,18.23
VCCPINT on L3_PWR: 68.55,15.06 68.55,17.92 46.33,17.92 46.33,33.16 51.73,33.16 51.73,36.65 55.4,36.65 57.31,34.74 78.4,34.74 78.4,23.95 83.79,23.95 83.79,15.06
VDD_INTERFACE on TOP: 31.98,13.66 31.98,17.22 32.1,17.35 32.1,17.97 34.64,17.97 34.64,13.66
VDD_INTERFACE on L8_PWR: 27.91,14.74 27.91,27.76 29.69,27.76 36.04,21.41 36.17,21.41 36.17,14.74
VIN on TOP: 79.73,57.35 79.73,60.02 84.81,60.02 84.81,59.51 86.71,59.51 87.09,59.13 87.09,57.35
VIN on TOP: 37.06,51.76 37.06,52.4 35.91,52.4 35.41,51.89 35.41,49.98 36.55,49.98 36.93,50.37 36.93,51.64 ; 1 cut-out
VIN on TOP: 91.92,46.24 90.33,46.24 89.51,47.06 89.51,52.52 91.67,52.52 91.92,52.27 ; 1 cut-out
VIN on TOP: 90.78,15.95 90.78,17.47 90.65,17.6 90.65,17.9 91.03,17.9 91.08,17.96 91.08,18.36 90.88,18.36 90.65,18.13 90.65,19.12 91.29,19.12 91.29,19.76 94.08,19.76 95.6,18.23 95.6,15.95 ; 1 cut-out
VIN on TOP: 50.52,11.5 53.31,11.5 53.31,14.04 50.77,14.04 50.52,13.79
VIN on TOP: 92.05,39.95 92.05,35.76 89.89,35.76 89.89,40.21 89.38,40.71 89.38,41.35 90.4,42.36 91.41,42.36 91.41,40.59 ; 1 cut-out
VIN on L3_PWR: 57.57,8.71 55.03,11.25 51.09,11.25 51.09,17.28 67.92,17.28 67.92,14.42 84.43,14.42 84.43,24.58 79.03,24.58 79.03,40.46 84.11,40.46 84.11,56.97 77.76,56.97 77.76,67.88 88.09,67.01 98.4,65.83 98.4,41.23 97.13,39.96 97.13,36.33 102.53,36.33 102.53,29.35 108.5,29.35 108.5,8.71
VIN on L8_PWR: 34.9,49.35 34.9,60.14 49.84,60.14 52.28,59.26 54.71,60.14 84.43,60.14 84.43,50.62 38.71,50.62 38.71,49.35
VIN_5V_USB on TOP: 99.67,38.94 99.67,38.97 100.3,38.97 100.3,39.37 99.67,39.37 99.67,41.48 100.94,41.48 100.94,39.06 100.81,38.94
VIN_5V_USB on TOP: 100.43,52.91 100.18,53.16 100.18,54.81 101.57,54.81 102.08,54.3 102.08,54.04 101.56,54.04 101.56,52.92 102.08,52.92 102.08,52.91
VIN_5V_USB on TOP: 99.03,58.62 102.97,58.62 102.97,61.29 99.03,61.29
VIN_5V_USB on L8_PWR: 99.03,39.51 99.03,65.75 101.26,65.45 103.48,65.13 103.48,55.7 101.89,55.7 101.89,39.51
VIN_5V_USB_DATA on TOP: 99.67,37.03 99.67,38.19 100.64,38.19 100.64,38.27 100.65,38.27 100.65,38.67 99.67,38.67 99.67,38.68 100.81,38.68 101.32,38.17 102.33,38.17 103.8,36.71 103.8,36.14 103.35,36.14 102.46,37.03
VIN_5V_USB_DATA on BOTTOM: 99.67,38.55 102.46,38.55 102.46,36.97 99.67,36.97
VIN_5V_USB_POWER on TOP: 103.35,43.76 104.75,43.76 104.75,45.03 103.35,45.03
